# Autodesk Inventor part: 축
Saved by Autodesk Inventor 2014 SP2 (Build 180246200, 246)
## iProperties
Created: 2024-04
Part Number: 축
Material: Generic
Document SubType Name: Modeling
Designer: Administrator
Density: 1 g/cm^3
Appearance: Default
Author: Administrator
Author: jhkim
Creation Date: 2024-04-08
Sending System: Autodesk Inventor 2025
Preprocessor: ST-DEVELOPER v20
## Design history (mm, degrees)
node "축1"
node "솔리드1"
node "기준1"
